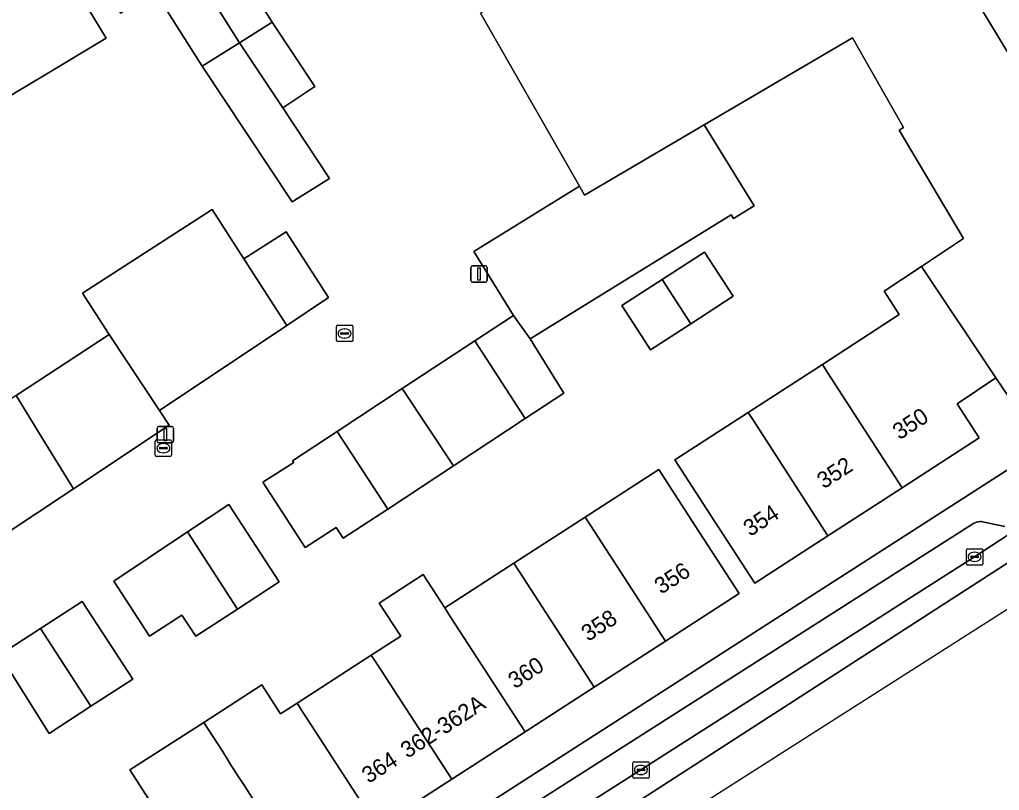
# Model space of a CAD drawing. Extents: x 159217 to 160349, y 381246 to 382172.
# Drawn here: x 159998.6 to 160058.5, y 381550.9 to 381598 of the extents above; entities that cross this region are included whole.
import ezdxf

# ---------------------------------------------------------------- set-up
doc = ezdxf.new("R2010")
doc.units = 0
for name, color, linetype in [('IMGEO_Erf', 7, 'Continuous'), ('IMGEO_Kolk', 7, 'Continuous'), ('IMGEO_Lichtmast', 7, 'Continuous'), ('IMGEO_Pand', 7, 'Continuous'), ('IMGEO_Pand_nummerreeks', 7, 'Continuous'), ('IMGEO_Parkeervlak_open', 7, 'Continuous'), ('IMGEO_Rijbaan_lokaal_gesloten', 7, 'Continuous'), ('IMGEO_Voetpad_open', 7, 'Continuous')]:
    doc.layers.add(name, color=color, linetype=linetype)

msp = doc.modelspace()

# ---------------------------------------------------------------- linework, layer by layer
at = {"layer": 'IMGEO_Erf'}
for points in [[(160049.627, 381611.625), (160059.237, 381595.737), (160060.16, 381596.34), (160064.034, 381590.405), (160065.441, 381591.324), (160069.627, 381594.058), (160076.071, 381584.244), (160076.584, 381584.042), (160076.802, 381583.707), (160078.623, 381584.859), (160080.507, 381586.051), (160079.028, 381586.399), (160074.124, 381593.909), (160073.116, 381594.445), (160072.253, 381595.767), (160070.382, 381598.632)], [(160011.177, 381602.484), (160014.078, 381597.892), (160016.683, 381593.956), (160014.72, 381592.657), (160017.575, 381588.342), (160015.293, 381586.9), (160009.804, 381595.193), (160006.904, 381599.784)], [(160002.895, 381598.634), (160003.926, 381596.913), (160000, 381594.557), (159997.606, 381593.12)], [(160024.711, 381548.473), (160061.199, 381571.915), (160058.326, 381576.141), (160055.953, 381574.559), (160057.305, 381572.471), (160052.6, 381569.428), (160048.061, 381566.491), (160043.582, 381563.594), (160040.864, 381567.791), (160038.703, 381571.128), (160043.187, 381574.032), (160047.722, 381576.969), (160052.421, 381580.012), (160051.5, 381581.434), (160053.781, 381582.955), (160056.352, 381584.668), (160052.409, 381591.278), (160052.674, 381591.451), (160049.549, 381596.935), (160040.486, 381591.604), (160043.542, 381586.659), (160042.278, 381585.878), (160042.135, 381586.111), (160029.854, 381578.522), (160031.914, 381575.209), (160029.538, 381573.665), (160025.163, 381570.772), (160021.139, 381568.107), (160018.412, 381566.334), (160017.981, 381566.996), (160016.102, 381565.775), (160013.513, 381569.756), (160015.4, 381570.966), (160015.327, 381571.078), (160018.054, 381572.871), (160022.028, 381575.483), (160026.47, 381578.403), (160028.829, 381579.954), (160026.411, 381583.867), (160032.866, 381587.856), (160026.803, 381598.447)], [(159998.426, 381575.058), (160004.104, 381578.804), (160002.468, 381581.329), (160010.407, 381586.435), (160012.352, 381583.411), (160014.931, 381585.07), (160017.516, 381581.053), (160014.967, 381579.346), (160007.19, 381574.138), (160007.781, 381573.246), (160001.919, 381569.363), (159997.433, 381566.391)], [(160006.52, 381550.399), (160005.38, 381552.169), (160009.889, 381555.076), (160013.451, 381557.372), (160013.817, 381556.804), (160014.588, 381555.608), (160015.6, 381556.262), (160020.137, 381559.191), (160021.933, 381560.351), (160020.624, 381562.377), (160023.316, 381564.117), (160024.626, 381562.09), (160028.858, 381564.822), (160033.214, 381567.634), (160037.714, 381570.54), (160039.906, 381567.155), (160042.624, 381562.958), (160038.121, 381560.047), (160033.763, 381557.23), (160029.535, 381554.496), (160025.052, 381551.597), (160020.518, 381548.666)]]:
    msp.add_lwpolyline(points, dxfattribs=at)
for points in [[(160040.515, 381583.835), (160042.265, 381581.129), (160039.668, 381579.45), (160037.211, 381577.86), (160036.88, 381578.372), (160035.461, 381580.566), (160035.811, 381580.793), (160037.917, 381582.154)], [(160014.499, 381563.663), (160011.948, 381562.004), (160009.397, 381560.345), (160008.56, 381561.632), (160006.578, 381560.343), (160004.391, 381563.707), (160008.893, 381566.72), (160011.415, 381568.407)], [(160005.547, 381557.721), (160002.996, 381556.062), (160000.444, 381554.403), (159997.411, 381559.21), (159999.912, 381560.822), (160002.462, 381562.465)]]:
    msp.add_lwpolyline(points, close=True, dxfattribs=at)
at = {"layer": 'IMGEO_Kolk'}
for p, q in [((160018, 381578.431), (160018, 381579.283)), ((160018.075, 381579.357), (160018.927, 381579.357)), ((160018.259, 381578.851), (160018.259, 381578.863)), ((160018.697, 381578.814), (160018.299, 381578.814)), ((160018.302, 381578.9), (160018.7, 381578.9)), ((160018.488, 381579.137), (160018.513, 381579.137)), ((160018.743, 381578.863), (160018.743, 381578.851)), ((160019.001, 381579.283), (160019.001, 381578.431)), ((160018.927, 381578.357), (160018.075, 381578.357)), ((160018.511, 381578.577), (160018.486, 381578.577)), ((160006.922, 381571.419), (160006.922, 381572.271)), ((160006.997, 381572.345), (160007.849, 381572.345)), ((160007.923, 381572.271), (160007.923, 381571.419)), ((160007.181, 381571.839), (160007.181, 381571.851)), ((160007.619, 381571.802), (160007.221, 381571.802)), ((160007.224, 381571.888), (160007.622, 381571.888)), ((160007.41, 381572.125), (160007.435, 381572.125)), ((160007.665, 381571.851), (160007.665, 381571.839)), ((160007.849, 381571.345), (160006.997, 381571.345)), ((160007.433, 381571.565), (160007.408, 381571.565)), ((160056.523, 381564.773), (160056.523, 381565.625)), ((160056.598, 381565.699), (160057.45, 381565.699)), ((160057.524, 381565.625), (160057.524, 381564.773)), ((160056.782, 381565.193), (160056.782, 381565.205)), ((160057.22, 381565.156), (160056.822, 381565.156)), ((160056.825, 381565.242), (160057.223, 381565.242)), ((160057.011, 381565.479), (160057.036, 381565.479)), ((160057.266, 381565.205), (160057.266, 381565.193)), ((160057.45, 381564.699), (160056.598, 381564.699)), ((160057.034, 381564.919), (160057.009, 381564.919)), ((160036.125, 381551.744), (160036.125, 381552.596)), ((160036.2, 381552.67), (160037.052, 381552.67)), ((160036.613, 381552.45), (160036.638, 381552.45)), ((160037.126, 381552.596), (160037.126, 381551.744)), ((160036.384, 381552.164), (160036.384, 381552.176)), ((160036.822, 381552.127), (160036.424, 381552.127)), ((160036.427, 381552.213), (160036.825, 381552.213)), ((160036.636, 381551.89), (160036.611, 381551.89)), ((160036.868, 381552.176), (160036.868, 381552.164)), ((160037.052, 381551.67), (160036.2, 381551.67))]:
    msp.add_line(p, q, dxfattribs=at)
for points in [[(160018, 381578.431), (160018, 381579.283)], [(160018.075, 381579.357), (160018.927, 381579.357)], [(160019.001, 381579.283), (160019.001, 381578.431)], [(160018.927, 381578.357), (160018.075, 381578.357)], [(160006.922, 381571.419), (160006.922, 381572.271)], [(160006.997, 381572.345), (160007.849, 381572.345)], [(160007.923, 381572.271), (160007.923, 381571.419)], [(160007.849, 381571.345), (160006.997, 381571.345)], [(160056.523, 381564.773), (160056.523, 381565.625)], [(160056.598, 381565.699), (160057.45, 381565.699)], [(160057.524, 381565.625), (160057.524, 381564.773)], [(160057.45, 381564.699), (160056.598, 381564.699)], [(160036.125, 381551.744), (160036.125, 381552.596)], [(160036.2, 381552.67), (160037.052, 381552.67)], [(160037.126, 381552.596), (160037.126, 381551.744)], [(160037.052, 381551.67), (160036.2, 381551.67)]]:
    msp.add_lwpolyline(points, dxfattribs=at)
for centre, radius, start, end in [((160018.077, 381579.281), 0.0765, 91.55205, 178.44795), ((160018.077, 381579.281), 0.0765, 91.55205, 178.44795), ((160018.299, 381578.86), 0.0403, 85.87752, 175.75265), ((160018.296, 381578.85), 0.0366, 178.93798, 274.71019), ((160018.7, 381578.857), 0.043, 264.86636, 352.45326), ((160018.704, 381578.862), 0.0386, 1.73085, 96.63898), ((160018.925, 381579.281), 0.0765, 1.55205, 88.44795), ((160018.925, 381579.281), 0.0765, 1.55205, 88.44795), ((160018.077, 381578.433), 0.0765, 181.55205, 268.44795), ((160018.077, 381578.433), 0.0765, 181.55205, 268.44795), ((160018.925, 381578.433), 0.0765, 271.55205, 358.44795), ((160018.925, 381578.433), 0.0765, 271.55205, 358.44795), ((160006.999, 381572.269), 0.0765, 91.55205, 178.44795), ((160006.999, 381572.269), 0.0765, 91.55205, 178.44795), ((160007.847, 381572.269), 0.0765, 1.55205, 88.44795), ((160007.847, 381572.269), 0.0765, 1.55205, 88.44795), ((160007.221, 381571.848), 0.0403, 85.87752, 175.75265), ((160007.218, 381571.838), 0.0366, 178.93798, 274.71019), ((160007.622, 381571.845), 0.043, 264.86636, 352.45326), ((160007.626, 381571.85), 0.0386, 1.73085, 96.63898), ((160006.999, 381571.421), 0.0765, 181.55205, 268.44795), ((160006.999, 381571.421), 0.0765, 181.55205, 268.44795), ((160007.847, 381571.421), 0.0765, 271.55205, 358.44795), ((160007.847, 381571.421), 0.0765, 271.55205, 358.44795), ((160056.6, 381565.623), 0.0765, 91.55205, 178.44795), ((160056.6, 381565.623), 0.0765, 91.55205, 178.44795), ((160057.448, 381565.623), 0.0765, 1.55205, 88.44795), ((160057.448, 381565.623), 0.0765, 1.55205, 88.44795), ((160056.822, 381565.202), 0.0403, 85.87752, 175.75265), ((160056.819, 381565.192), 0.0366, 178.93798, 274.71019), ((160057.223, 381565.199), 0.043, 264.86636, 352.45326), ((160057.227, 381565.204), 0.0386, 1.73085, 96.63898), ((160056.6, 381564.775), 0.0765, 181.55205, 268.44795), ((160056.6, 381564.775), 0.0765, 181.55205, 268.44795), ((160057.448, 381564.775), 0.0765, 271.55205, 358.44795), ((160057.448, 381564.775), 0.0765, 271.55205, 358.44795), ((160036.202, 381552.594), 0.0765, 91.55205, 178.44795), ((160036.202, 381552.594), 0.0765, 91.55205, 178.44795), ((160037.05, 381552.594), 0.0765, 1.55205, 88.44795), ((160037.05, 381552.594), 0.0765, 1.55205, 88.44795), ((160036.424, 381552.173), 0.0403, 85.87752, 175.75265), ((160036.421, 381552.163), 0.0366, 178.93798, 274.71019), ((160036.825, 381552.17), 0.043, 264.86636, 352.45326), ((160036.829, 381552.175), 0.0386, 1.73085, 96.63898), ((160036.202, 381551.746), 0.0765, 181.55205, 268.44795), ((160036.202, 381551.746), 0.0765, 181.55205, 268.44795), ((160037.05, 381551.746), 0.0765, 271.55205, 358.44795), ((160037.05, 381551.746), 0.0765, 271.55205, 358.44795)]:
    msp.add_arc(centre, radius, start, end, dxfattribs=at)
for centre, major_axis, ratio, start_param, end_param in [((160018.487, 381578.857), (-0.387, 0.002), 0.722429, 4.712389, 7.853982), ((160018.512, 381578.857), (-0.39, 0.002), 0.717154, 1.570796, 4.712389), ((160007.409, 381571.845), (-0.387, 0.002), 0.722429, 4.712389, 7.853982), ((160007.434, 381571.845), (-0.39, 0.002), 0.717154, 1.570796, 4.712389), ((160057.01, 381565.199), (-0.387, 0.002), 0.722429, 4.712389, 7.853982), ((160057.035, 381565.199), (-0.39, 0.002), 0.717154, 1.570796, 4.712389), ((160036.612, 381552.17), (-0.387, 0.002), 0.722429, 4.712389, 7.853982), ((160036.637, 381552.17), (-0.39, 0.002), 0.717154, 1.570796, 4.712389)]:
    msp.add_ellipse(centre, major_axis=major_axis, ratio=ratio, start_param=start_param, end_param=end_param, dxfattribs=at)
at = {"layer": 'IMGEO_Lichtmast'}
for p, q in [((160026.229, 381582.095), (160026.229, 381582.895)), ((160026.229, 381582.895), (160026.229, 381582.095)), ((160026.329, 381582.995), (160027.119, 381582.995)), ((160027.119, 381582.995), (160026.329, 381582.995)), ((160027.219, 381582.895), (160027.219, 381582.095)), ((160027.219, 381582.095), (160027.219, 381582.895)), ((160027.119, 381581.995), (160026.329, 381581.995)), ((160026.329, 381581.995), (160027.119, 381581.995)), ((160007.044, 381572.268), (160007.044, 381573.068)), ((160007.044, 381573.068), (160007.044, 381572.268)), ((160007.144, 381573.168), (160007.934, 381573.168)), ((160007.934, 381573.168), (160007.144, 381573.168)), ((160008.034, 381573.068), (160008.034, 381572.268)), ((160008.034, 381572.268), (160008.034, 381573.068)), ((160007.934, 381572.168), (160007.144, 381572.168)), ((160007.144, 381572.168), (160007.934, 381572.168))]:
    msp.add_line(p, q, dxfattribs=at)
for points in [[(160026.649, 381582.87), (160026.799, 381582.87), (160026.799, 381582.12), (160026.649, 381582.12), (160026.649, 381582.87)], [(160007.464, 381573.043), (160007.614, 381573.043), (160007.614, 381572.293), (160007.464, 381572.293), (160007.464, 381573.043)]]:
    msp.add_lwpolyline(points, dxfattribs=at)
for centre, start, end in [((160026.329, 381582.895), 90, 180), ((160026.329, 381582.895), 90, 180), ((160027.119, 381582.895), 0, 90), ((160027.119, 381582.895), 360, 90), ((160026.329, 381582.095), 180, 270), ((160026.329, 381582.095), 180, 270), ((160027.119, 381582.095), 270, 0), ((160027.119, 381582.095), 270, 0), ((160007.144, 381573.068), 90, 180), ((160007.144, 381573.068), 90, 180), ((160007.934, 381573.068), 0, 90), ((160007.934, 381573.068), 360, 90), ((160007.144, 381572.268), 180, 270), ((160007.144, 381572.268), 180, 270), ((160007.934, 381572.268), 270, 0), ((160007.934, 381572.268), 270, 0)]:
    msp.add_arc(centre, 0.1, start, end, dxfattribs=at)
at = {"layer": 'IMGEO_Pand'}
for points in [[(160009.048, 381611.466), (160004.524, 381608.608), (160009.187, 381601.226), (160012.087, 381596.635), (160014.078, 381597.892), (160011.177, 381602.484), (160013.711, 381604.084), (160011.718, 381607.239)], [(160064.034, 381590.405), (160060.16, 381596.34), (160059.237, 381595.737), (160049.627, 381611.625), (160026.803, 381598.447), (160032.866, 381587.856), (160033.181, 381587.306), (160040.486, 381591.604), (160049.549, 381596.935), (160052.674, 381591.451), (160052.409, 381591.278), (160056.352, 381584.668), (160053.781, 381582.955), (160058.326, 381576.141), (160061.199, 381571.915), (160071.796, 381578.997), (160071.673, 381579.183), (160071.758, 381579.255), (160071.216, 381580.08)], [(160004.524, 381608.608), (160000, 381605.75), (159999.858, 381605.66), (160000, 381605.453), (160002.682, 381601.534), (160004.792, 381598.449), (160006.904, 381599.784), (160009.804, 381595.193), (160012.087, 381596.635), (160009.187, 381601.226)], [(159992.76, 381601.198), (159995.332, 381596.91), (159996.573, 381594.842), (159997.606, 381593.12), (160000, 381594.557), (160003.926, 381596.913), (160002.895, 381598.634), (160001.655, 381600.703), (160000, 381603.46), (159999.082, 381604.99)], [(160014.078, 381597.892), (160012.087, 381596.635), (160014.72, 381592.657), (160016.683, 381593.956)], [(160014.72, 381592.657), (160012.087, 381596.635), (160009.804, 381595.193), (160015.293, 381586.9), (160017.575, 381588.342)], [(160028.829, 381579.954), (160029.854, 381578.522), (160042.135, 381586.111), (160042.278, 381585.878), (160043.542, 381586.659), (160040.486, 381591.604), (160033.181, 381587.306), (160032.866, 381587.856), (160026.411, 381583.867)], [(160007.19, 381574.138), (160014.967, 381579.346), (160012.352, 381583.411), (160010.407, 381586.435), (160002.468, 381581.329), (160004.104, 381578.804)], [(160012.352, 381583.411), (160014.967, 381579.346), (160017.516, 381581.053), (160014.931, 381585.07)], [(160039.668, 381579.45), (160042.265, 381581.129), (160040.515, 381583.835), (160037.917, 381582.154)], [(160047.722, 381576.969), (160048.038, 381576.471), (160052.6, 381569.428), (160057.305, 381572.471), (160055.953, 381574.559), (160058.326, 381576.141), (160053.781, 381582.955), (160051.5, 381581.434), (160052.421, 381580.012)], [(160039.668, 381579.45), (160037.917, 381582.154), (160035.811, 381580.793), (160035.461, 381580.566), (160036.88, 381578.372), (160037.211, 381577.86)], [(160028.829, 381579.954), (160026.47, 381578.403), (160029.538, 381573.665), (160031.914, 381575.209), (160029.854, 381578.522)], [(160001.919, 381569.363), (160007.781, 381573.246), (160007.19, 381574.138), (160004.104, 381578.804), (159998.426, 381575.058), (160000, 381572.491)], [(160029.538, 381573.665), (160026.47, 381578.403), (160022.028, 381575.483), (160025.163, 381570.772)], [(160047.722, 381576.969), (160043.187, 381574.032), (160043.501, 381573.532), (160048.061, 381566.491), (160052.6, 381569.428), (160048.038, 381576.471)], [(160022.028, 381575.483), (160018.054, 381572.871), (160021.139, 381568.107), (160025.163, 381570.772)], [(160001.919, 381569.363), (160000, 381572.491), (159998.426, 381575.058), (159993.793, 381572.001), (159997.433, 381566.391)], [(160048.061, 381566.491), (160043.501, 381573.532), (160043.187, 381574.032), (160038.703, 381571.128), (160040.864, 381567.791), (160043.582, 381563.594)], [(160018.054, 381572.871), (160015.327, 381571.078), (160015.4, 381570.966), (160013.513, 381569.756), (160016.102, 381565.775), (160017.981, 381566.996), (160018.412, 381566.334), (160021.139, 381568.107)], [(160033.214, 381567.634), (160033.55, 381567.106), (160038.121, 381560.047), (160042.624, 381562.958), (160039.906, 381567.155), (160037.714, 381570.54)], [(160008.893, 381566.72), (160011.948, 381562.004), (160014.499, 381563.663), (160011.415, 381568.407)], [(160033.214, 381567.634), (160028.858, 381564.822), (160029.194, 381564.285), (160033.763, 381557.23), (160038.121, 381560.047), (160033.55, 381567.106)], [(160008.893, 381566.72), (160004.391, 381563.707), (160006.578, 381560.343), (160008.56, 381561.632), (160009.397, 381560.345), (160011.948, 381562.004)], [(160028.858, 381564.822), (160024.626, 381562.09), (160024.968, 381561.548), (160029.535, 381554.496), (160033.763, 381557.23), (160029.194, 381564.285)], [(160024.626, 381562.09), (160023.316, 381564.117), (160020.624, 381562.377), (160021.933, 381560.351), (160020.137, 381559.191), (160020.487, 381558.646), (160025.052, 381551.597), (160029.535, 381554.496), (160024.968, 381561.548)], [(159999.912, 381560.822), (160002.996, 381556.062), (160005.547, 381557.721), (160002.462, 381562.465)], [(159999.912, 381560.822), (159997.411, 381559.21), (160000.444, 381554.403), (160002.996, 381556.062)], [(160020.518, 381548.666), (160025.052, 381551.597), (160020.487, 381558.646), (160020.137, 381559.191), (160015.6, 381556.262), (160015.956, 381555.711)], [(160015.6, 381556.262), (160014.588, 381555.608), (160013.817, 381556.804), (160013.451, 381557.372), (160009.889, 381555.076), (160011.028, 381553.31), (160011.38, 381552.748), (160011.573, 381552.45), (160011.652, 381552.328), (160012.061, 381551.696), (160012.314, 381551.307), (160012.71, 381550.694), (160014.026, 381548.662), (160014.315, 381548.216), (160014.549, 381547.855), (160015.103, 381546.999), (160015.477, 381546.422), (160015.94, 381545.707), (160020.518, 381548.666), (160015.956, 381555.711)], [(160009.889, 381555.076), (160005.38, 381552.169), (160006.52, 381550.399), (160006.869, 381549.826), (160011.426, 381542.788), (160015.94, 381545.707), (160015.477, 381546.422), (160015.103, 381546.999), (160014.549, 381547.855), (160014.315, 381548.216), (160014.026, 381548.662), (160012.71, 381550.694), (160012.314, 381551.307), (160012.061, 381551.696), (160011.652, 381552.328), (160011.573, 381552.45), (160011.38, 381552.748), (160011.028, 381553.31)]]:
    msp.add_lwpolyline(points, close=True, dxfattribs=at)
at = {"layer": 'IMGEO_Parkeervlak_open'}
for points in [[(160058.871, 381567.062), (160057.613, 381567.33), (160057.534, 381567.345), (160057.454, 381567.354), (160057.373, 381567.355), (160057.293, 381567.348), (160057.213, 381567.335), (160057.135, 381567.315), (160057.059, 381567.287), (160056.986, 381567.254), (160056.916, 381567.213), (160056.865, 381567.178), (160024.724, 381546.701)], [(160025.868, 381545.322), (160036.622, 381552.169), (160057.02, 381565.198), (160060.2, 381567.27)]]:
    msp.add_lwpolyline(points, dxfattribs=at)
at = {"layer": 'IMGEO_Rijbaan_lokaal_gesloten'}
for points in [[(160103.074, 381595.46), (160087.579, 381585.252), (160070.937, 381574.339), (160069.367, 381573.319), (160063.293, 381569.303), (160060.34, 381567.361), (160060.2, 381567.27), (160057.02, 381565.198), (160036.622, 381552.169), (160025.868, 381545.322), (160022.808, 381543.38), (160015.497, 381538.623), (160009.367, 381534.719), (160008.705, 381534.306), (160004.248, 381531.556), (160001.488, 381529.889), (160002.266, 381528.592), (160006.52, 381531.153), (160035.773, 381549.819), (160074.47, 381574.782), (160108.254, 381596.98)], [(160108.254, 381596.98), (160074.47, 381574.782), (160035.773, 381549.819), (160006.52, 381531.153), (160002.266, 381528.592), (160002.872, 381527.582), (160002.872, 381527.582), (160025.352, 381540.55), (160068.226, 381567.865), (160095.673, 381586.064)]]:
    msp.add_lwpolyline(points, dxfattribs=at)
at = {"layer": 'IMGEO_Voetpad_open'}
for points in [[(160088.964, 381591.573), (160086.871, 381590.207), (160083.94, 381588.293), (160081.847, 381586.926), (160080.717, 381586.188), (160080.507, 381586.051), (160078.623, 381584.859), (160076.802, 381583.707), (160075.656, 381582.963), (160073.55, 381581.596), (160071.216, 381580.08), (160071.758, 381579.255), (160071.673, 381579.183), (160071.796, 381578.997), (160061.199, 381571.915), (160024.711, 381548.473), (160000, 381532.468), (159997.877, 381531.093)], [(160024.724, 381546.701), (160056.865, 381567.178), (160056.916, 381567.213), (160056.986, 381567.254), (160057.059, 381567.287), (160057.135, 381567.315), (160057.213, 381567.335), (160057.293, 381567.348), (160057.373, 381567.355), (160057.454, 381567.354), (160057.534, 381567.345), (160057.613, 381567.33), (160058.871, 381567.062)]]:
    msp.add_lwpolyline(points, dxfattribs=at)

# ---------------------------------------------------------------- texts
at = {"layer": 'IMGEO_Pand_nummerreeks'}
for s, rotation, p in [('350', 32.89312, (160052.43, 381572.319)), ('352', 32.90524, (160047.802, 381569.324)), ('354', 32.89463, (160043.297, 381566.41)), ('356', 32.88322, (160037.861, 381562.88)), ('358', 32.88322, (160033.392, 381559.99)), ('360', 32.88322, (160028.919, 381557.099)), ('362-362A', 32.88322, (160022.343, 381552.847)), ('364', 32.88322, (160019.971, 381551.314))]:
    msp.add_text(s, height=1, rotation=rotation, dxfattribs=at).set_placement(p)

doc.saveas('drawing.dxf')
